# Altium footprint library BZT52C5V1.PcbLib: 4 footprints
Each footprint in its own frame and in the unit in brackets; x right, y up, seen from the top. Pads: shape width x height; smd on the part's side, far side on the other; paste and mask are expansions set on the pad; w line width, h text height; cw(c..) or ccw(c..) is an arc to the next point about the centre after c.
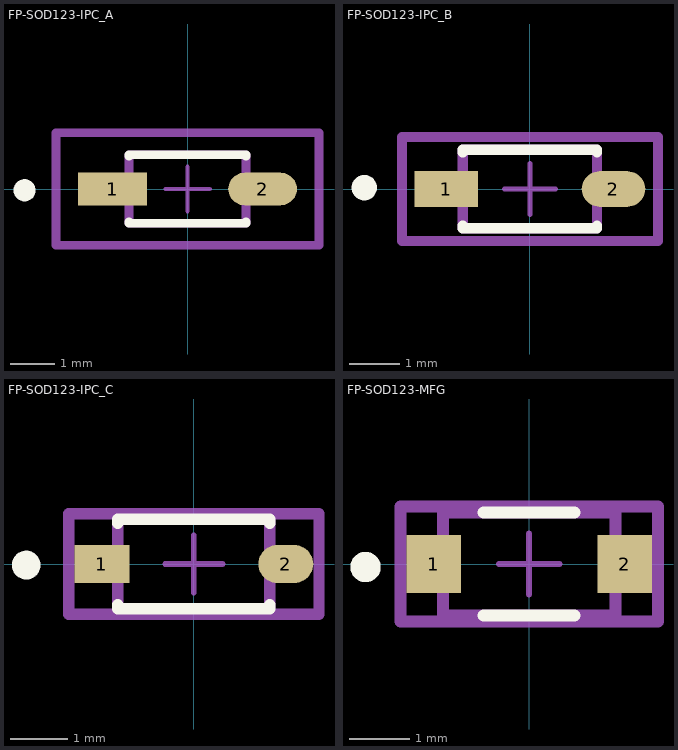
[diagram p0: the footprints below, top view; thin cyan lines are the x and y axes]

## FP-SOD123-IPC_A [mm]
pads (2):
  rect 1.557x0.742 smd paste+0 mask+0: 1(-1.7,0)
  rrect100% 1.557x0.742 smd paste+0 mask+0: 2(1.7,0)
Top Overlay:
  circle w0.25: c-3.695,-0.029 r0.125
  lines w0.2: -1.325,-0.746 -1.325,-0.775 1.325,-0.775 1.325,-0.746 ; -1.325,0.746 -1.325,0.775 1.325,0.775 1.325,0.746
Top Assembly:
  lines w0.2: -2.979,-1.275 2.979,-1.275 2.979,1.275 -2.979,1.275 -2.979,-1.275
  text ".Designator" at 0,0.188 h1
Top 3D Body:
  lines w0.2: -1.325,-0.775 1.325,-0.775 1.325,0.775 -1.325,0.775 -1.325,-0.775
Top Courtyard:
  lines w0.2: -2.979,-1.275 2.979,-1.275 2.979,1.275 -2.979,1.275 -2.979,-1.275
Top Component Center:
  lines w0.1: -0.5,0 0.5,0 ; 0,-0.5 0,0.5
3D body "Diode_Diodes_Incorporated_BZT52C5V1-7-F_eec.STEP": height 0.25, standoff 0, extent -2.979,-1.275 2.979,1.275

## FP-SOD123-IPC_B [mm]
pads (2):
  rect 1.257x0.702 smd paste+0 mask+0: 1(-1.65,0)
  rrect100% 1.257x0.702 smd paste+0 mask+0: 2(1.65,0)
Top Overlay:
  circle w0.25: c-3.27,0.026 r0.125
  lines w0.2: -1.325,-0.726 -1.325,-0.775 1.325,-0.775 1.325,-0.726 ; -1.325,0.726 -1.325,0.775 1.325,0.775 1.325,0.726
Top Assembly:
  lines w0.2: -2.529,-1.025 2.529,-1.025 2.529,1.025 -2.529,1.025 -2.529,-1.025
  text ".Designator" at 0,0.188 h1
Top 3D Body:
  lines w0.2: -1.325,-0.775 1.325,-0.775 1.325,0.775 -1.325,0.775 -1.325,-0.775
Top Courtyard:
  lines w0.2: -2.529,-1.025 2.529,-1.025 2.529,1.025 -2.529,1.025 -2.529,-1.025
Top Component Center:
  lines w0.1: -0.5,0 0.5,0 ; 0,-0.5 0,0.5
3D body "Diode_Diodes_Incorporated_BZT52C5V1-7-F_eec.STEP": height 0.25, standoff 0, extent -2.529,-1.025 2.529,1.025

## FP-SOD123-IPC_C [mm]
pads (2):
  rect 0.957x0.662 smd paste+0 mask+0: 1(-1.6,0)
  rrect100% 0.957x0.662 smd paste+0 mask+0: 2(1.6,0)
Top Overlay:
  circle w0.25: c-2.92,-0.019 r0.125
  lines w0.2: -1.325,-0.706 -1.325,-0.775 1.325,-0.775 1.325,-0.706 ; -1.325,0.706 -1.325,0.775 1.325,0.775 1.325,0.706
Top Assembly:
  lines w0.2: -2.179,-0.875 2.179,-0.875 2.179,0.875 -2.179,0.875 -2.179,-0.875
  text ".Designator" at 0,0.188 h1
Top 3D Body:
  lines w0.2: -1.325,-0.775 1.325,-0.775 1.325,0.775 -1.325,0.775 -1.325,-0.775
Top Courtyard:
  lines w0.2: -2.179,-0.875 2.179,-0.875 2.179,0.875 -2.179,0.875 -2.179,-0.875
Top Component Center:
  lines w0.1: -0.5,0 0.5,0 ; 0,-0.5 0,0.5
3D body "Diode_Diodes_Incorporated_BZT52C5V1-7-F_eec.STEP": height 0.25, standoff 0, extent -2.179,-0.875 2.179,0.875

## FP-SOD123-MFG [mm]
pads (2):
  rect 0.9x0.95 smd paste+0 mask+0: 1(-1.575,0) 2(1.575,0)
Top Overlay:
  circle w0.25: c-2.7,-0.05 r0.125
  lines w0.2: -0.75,-0.85 0.75,-0.85 ; -0.75,0.85 0.75,0.85
Top Assembly:
  lines w0.2: -2.125,-0.95 2.125,-0.95 2.125,0.95 -2.125,0.95 -2.125,-0.95
  text ".Designator" at 0,-0.001 h1
Top 3D Body:
  lines w0.2: -1.425,-0.85 1.425,-0.85 1.425,0.85 -1.425,0.85 -1.425,-0.85
Top Courtyard:
  lines w0.2: -2.125,-0.95 2.125,-0.95 2.125,0.95 -2.125,0.95 -2.125,-0.95
Top Component Center:
  lines w0.1: -0.5,0 0.5,0 ; 0,-0.5 0,0.5
3D body "Diode_Diodes_Incorporated_BZT52C5V1-7-F_eec.STEP": height 0.25, standoff 0, extent -2.125,-0.95 2.125,0.95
